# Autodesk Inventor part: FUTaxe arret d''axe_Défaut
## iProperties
Shininess: 64.0
Length Units: 11269
Angle Units: 11279
Time Units: 11290
Mass Units: 11283
Length Display Precision: 3
Angle Display Precision: 2
Compacted: True
Part Number: FUTaxe arret d''axe_Défaut
Document SubType Name: Modeling
Created: 2006-11
Material: Par défaut
Designer: profs_sti
Density: 0.0
Volumn: 0.0
Area: 0.0
PropertySet Name: Model Information
Control State: 0
Master: False
Checked Out: False
Author: profs_sti
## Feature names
1. Base1
